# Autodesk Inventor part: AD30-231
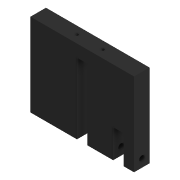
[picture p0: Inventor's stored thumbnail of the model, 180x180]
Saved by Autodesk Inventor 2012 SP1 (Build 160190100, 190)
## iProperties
Shininess: 0.0
Created: 2000-06
Part Number: AD30-231
Project: BONDING PRESS
Description: CAM GUIDE
Document SubType Name: Modeling
Designer: Ron
Material: Aluminum-6061-AHC
Density: 1 g/cm^3
Density: 0.0
Volumn: 0.0
Area: 0.0
PropertySet Name: Model Information
Control State: 0
Master: False
Checked Out: False
Title: CAM GUIDE
Author: Ron
Revision Number: 01
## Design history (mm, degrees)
node "Extrusion1" dims "d4" = 19.05, "d5" = 0
  sketch "Sketch1"
    geometry: L1 (-63.5, 101.6)-(63.5, 101.6); L2 (63.5, 101.6)-(63.5, 0); L3 (63.5, 0)-(-63.5, 0); L4 (-63.5, 0)-(-63.5, 101.6); L5 (-6.45, 0)-(6.45, 0); L6 (6.45, 0)-(6.45, 86.6); L7 (6.45, 86.6)-(-6.45, 86.6); L8 (-6.45, 86.6)-(-6.45, 0); 2 further points
    constraints: 16 end point, 4 parallel, 2 horizontal, 2 midpoint, 2 perpendicular, 1 coincident
    dimensions: "d0" = 127 distance of L1.start L1.end; "d1" = 101.6 distance of L1.end L2.end; "d2" = 12.9 distance between parallel lines of L6 L8; "d3" = 15 distance between parallel lines of L1 L7
node "Hole1" dims "d7" = 3.242, "d8" = 4, "d9" = 2, "d10" = 60 deg, "d11" = 12, "d12" = 118 deg, "d24" = 8
  sketch "Sketch2"
    geometry: L1 (0, 0)-(0, 19.05) reference; L2 (127, 0)-(127, 19.05) reference; L3 (47.625, 9.525)-(79.375, 9.525); L4 (47.625, 9.525)-(0, 9.525); L5 (79.375, 9.525)-(127, 9.525)
    constraints: 6 end point, 2 midpoint, 2 perpendicular, 1 collinear
    dimensions: "d6" = 31.75 distance of L3.end L3.start
node "Extrusion2" dims "d15" = 10, "d16" = 0
  sketch "Sketch3"
    geometry: L1 (0, 0)-(19.05, 0) reference; L2 (9.525, 0)-(9.525, 32.204); C1 r 3.175 at (9.525, 10)
    constraints: 2 end point, 1 centre point, 1 midpoint, 1 perpendicular, 1 point on line
    dimensions: "d13" = 6.35 diameter of C1; "d14" = 10 distance from line of L1 C1.centre
node "Extrusion3" dims "d20" = 10, "d21" = 0
  sketch "Sketch4"
    geometry: L1 (6.45, 0)-(63.5, 0) reference; L2 (63.5, 0)-(63.5, 101.6) reference; L3 (50.8, 0)-(37.9, 0); L4 (37.9, 0)-(37.9, 35); L5 (37.9, 35)-(50.8, 35); L6 (50.8, 35)-(50.8, 0)
    constraints: 8 end point, 2 parallel, 1 collinear, 1 horizontal, 1 perpendicular
    dimensions: "d17" = 12.9 distance between parallel lines of L4 L6; "d18" = 12.7 distance between parallel lines of L2 L6; "d19" = 35 distance between parallel lines of L5 L1
body "Solid1"
